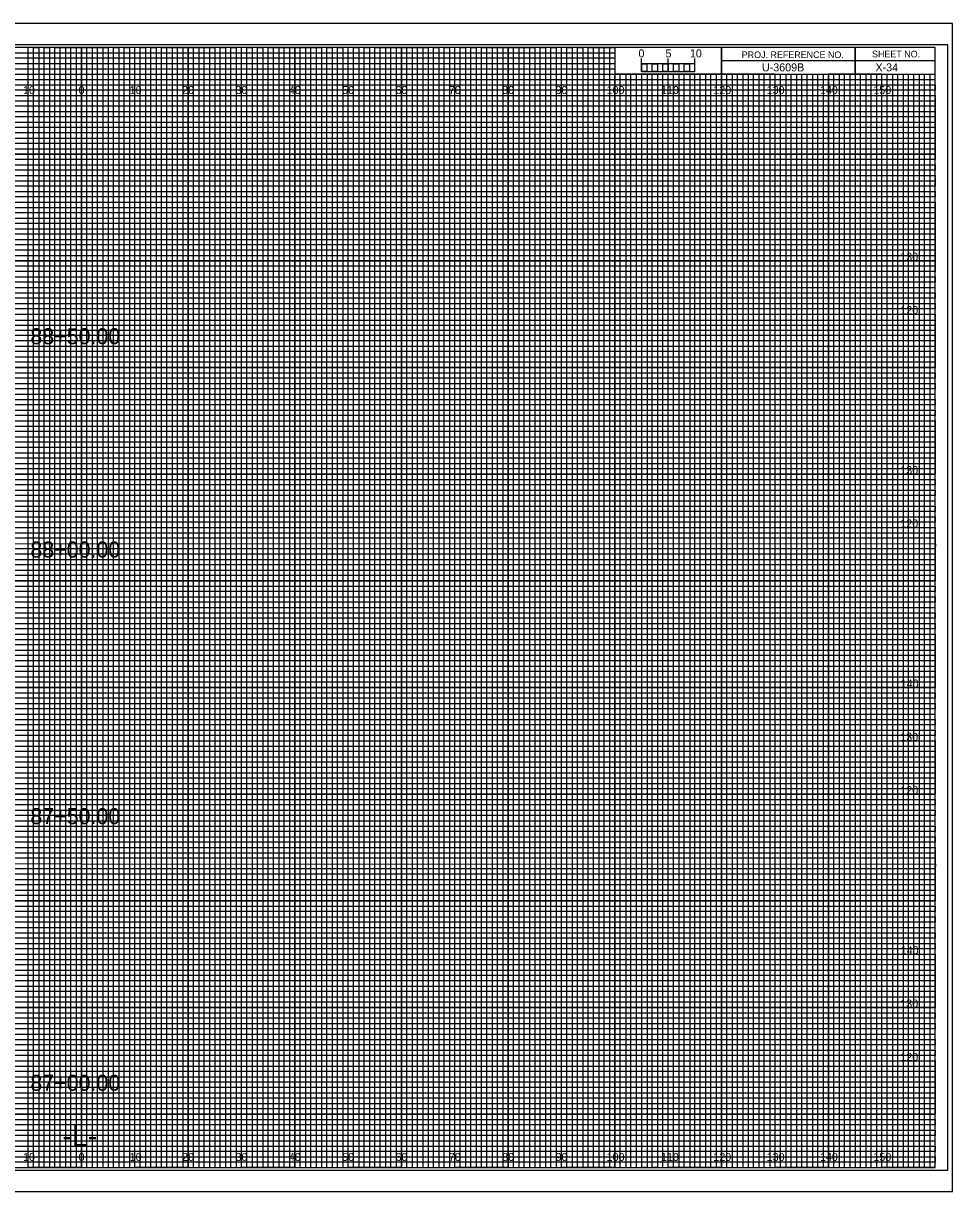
# Model space of a CAD drawing. Extents: x -13 to 329, y -17 to 10994.
# Drawn here: x 149.1 to 323.3, y 7035.5 to 7254.5 of the extents above; entities that cross this region are included whole.
import ezdxf

# ---------------------------------------------------------------- set-up
doc = ezdxf.new("R2010")
doc.units = 0
for name, color, linetype in [('Prop XS Alignment Label', 7, 'Continuous'), ('Prop XS Bar Scale Labels', 7, 'Continuous'), ('Prop XS Elevation Labels', 7, 'Continuous'), ('Prop XS Offset Labels', 7, 'Continuous'), ('Prop XS Project Number', 7, 'Continuous'), ('Prop XS Sheet Number', 7, 'Continuous'), ('Prop XS Station Labels', 7, 'Continuous'), ('Sheet Cross Section CELL', 7, 'Continuous'), ('Sheet Cross Section Grid Major CELL', 7, 'Continuous'), ('Sheet Cross Section Grid Middle CELL', 7, 'Continuous'), ('Sheet Cross Section Grid Minor 1 CELL', 7, 'Continuous'), ('Sheet Cross Section Grid Minor 2 CELL', 7, 'Continuous'), ('Sheet Cross Section Scale CELL', 7, 'Continuous'), ('Sheet Cutting Line CELL', 7, 'Continuous'), ('Sheet DOT Grid CELL', 7, 'Continuous'), ('Sheet Plot Border Inside CELL', 7, 'Continuous'), ('Sheet Plot Border Outside CELL', 7, 'Continuous')]:
    doc.layers.add(name, color=color, linetype=linetype)

msp = doc.modelspace()

# ---------------------------------------------------------------- linework, layer by layer
at = {"layer": 'Sheet Cross Section CELL'}
for p, q in [((305, 7250), (305, 7245)), ((305, 7245), (305, 7250)), ((280, 7247.5), (280, 7245)), ((320, 7247.49), (280, 7247.49)), ((280, 7245), (320, 7245))]:
    msp.add_line(p, q, dxfattribs=at)
for points in [[(320, 7250), (0, 7250), (0, 7040), (320, 7040)], [(280, 7250), (260, 7250), (260, 7245.03), (280, 7245.03)], [(320, 7250), (280, 7250), (280, 7245), (320, 7245)]]:
    msp.add_lwpolyline(points, close=True, dxfattribs=at)
at = {"layer": 'Sheet Cross Section Grid Major CELL'}
for p, q in [((150, 7250), (140, 7250)), ((150, 7040), (150, 7250)), ((170, 7250), (160, 7250)), ((160, 7250), (160, 7040)), ((170, 7040), (170, 7250)), ((190, 7250), (180, 7250)), ((180, 7250), (180, 7040)), ((190, 7040), (190, 7250)), ((210, 7250), (200, 7250)), ((200, 7250), (200, 7040)), ((210, 7040), (210, 7250)), ((230, 7250), (220, 7250)), ((220, 7250), (220, 7040)), ((230, 7040), (230, 7250)), ((250, 7250), (240, 7250)), ((240, 7250), (240, 7040)), ((250, 7040), (250, 7250)), ((260, 7250), (260, 7040)), ((270, 7040), (270, 7245)), ((290, 7245), (280, 7245)), ((280, 7245), (280, 7040)), ((290, 7040), (290, 7245)), ((310, 7245), (300, 7245)), ((300, 7245), (300, 7040)), ((310, 7040), (310, 7245)), ((160, 7040), (150, 7040)), ((180, 7040), (170, 7040)), ((200, 7040), (190, 7040)), ((220, 7040), (210, 7040)), ((240, 7040), (230, 7040)), ((260, 7040), (250, 7040)), ((280, 7040), (270, 7040)), ((300, 7040), (290, 7040)), ((320, 7040), (310, 7040)), ((320, 7040), (320, 7040))]:
    msp.add_line(p, q, dxfattribs=at)
for points in [[(0, 7240), (320, 7240), (320, 7230), (0, 7230)], [(0, 7220), (320, 7220), (320, 7210), (0, 7210)], [(0, 7200), (320, 7200), (320, 7190), (0, 7190)], [(0, 7180), (320, 7180), (320, 7170), (0, 7170)], [(0, 7160), (320, 7160), (320, 7150), (0, 7150)], [(0, 7140), (320, 7140), (320, 7130), (0, 7130)], [(0, 7120), (320, 7120), (320, 7110), (0, 7110)], [(0, 7100), (320, 7100), (320, 7090), (0, 7090)], [(0, 7080), (320, 7080), (320, 7070), (0, 7070)], [(0, 7060), (320, 7060), (320, 7050), (0, 7050)]]:
    msp.add_lwpolyline(points, dxfattribs=at)
at = {"layer": 'Sheet Cross Section Grid Middle CELL'}
for points in [[(145, 7040), (155, 7040), (155, 7250), (165, 7250), (165, 7040), (175, 7040), (175, 7250), (185, 7250), (185, 7040), (195, 7040), (195, 7250), (205, 7250), (205, 7040), (215, 7040), (215, 7250), (225, 7250), (225, 7040), (235, 7040), (235, 7250), (245, 7250), (245, 7040), (255, 7040), (255, 7250), (259.93, 7250), (260, 7250), (260, 7245), (264.99, 7245), (264.99, 7040), (275, 7040), (275, 7245), (285, 7245), (285, 7040), (295, 7040), (295, 7245), (305, 7245), (305, 7040), (315, 7040), (315, 7245)], [(0, 7245), (275, 7245)], [(0, 7225), (320, 7225), (320, 7235), (0, 7235)], [(0, 7205), (320, 7205), (320, 7215), (0, 7215)], [(0, 7185), (320, 7185), (320, 7195), (0, 7195)], [(0, 7165), (320, 7165), (320, 7175), (0, 7175)], [(0, 7145), (320, 7145), (320, 7155), (0, 7155)], [(0, 7125), (320, 7125), (320, 7135), (0, 7135)], [(0, 7105), (320, 7105), (320, 7115), (0, 7115)], [(0, 7085), (320, 7085), (320, 7095), (0, 7095)], [(0, 7065), (320, 7065), (320, 7075), (0, 7075)], [(0, 7045), (320, 7045), (320, 7055), (0, 7055)]]:
    msp.add_lwpolyline(points, dxfattribs=at)
at = {"layer": 'Sheet Cross Section Grid Minor 1 CELL'}
for p, q in [((0, 7249), (260, 7249)), ((260, 7249), (260, 7247.98)), ((260, 7247.98), (0, 7247.98)), ((0, 7247), (260, 7247)), ((260, 7247), (260, 7245.89)), ((260, 7245.89), (0, 7245.89)), ((0, 7244), (320, 7244))]:
    msp.add_line(p, q, dxfattribs=at)
for points in [[(0, 7243), (270, 7243), (320, 7243), (320, 7242), (0, 7242)], [(0, 7241), (320, 7241), (320, 7239), (0, 7239)], [(0, 7238), (320, 7238), (320, 7237), (0, 7236.98)], [(0, 7236), (320, 7236), (320, 7234), (0, 7234)], [(0, 7233), (320, 7233), (320, 7232), (0, 7232)], [(0, 7231), (320, 7231), (320, 7229), (0, 7229)], [(0, 7228), (320, 7228), (320, 7227), (0, 7227)], [(0, 7226), (320, 7226), (320, 7224), (0, 7224)], [(0, 7223), (320, 7223), (320, 7222), (0, 7222)], [(0, 7221), (320, 7221), (320, 7219), (0, 7219)], [(0, 7218), (320, 7218), (320, 7217), (0, 7217)], [(0, 7216), (320, 7216), (320, 7213.95), (320, 7213), (320, 7212), (0, 7212)], [(0, 7214), (320, 7214), (320, 7213), (0, 7213)], [(0, 7211), (320, 7211), (320, 7209), (0, 7209.03)], [(0, 7209.03), (320, 7209), (320, 7208), (0, 7208)], [(0, 7207), (320, 7207), (320, 7206), (0, 7206)], [(0, 7204), (320, 7204), (320, 7203), (0, 7203)], [(0, 7202), (320, 7202), (320, 7201), (0, 7201)], [(-0.07, 7198.89), (320, 7198.89), (320, 7197.88), (-0.07, 7197.88)], [(0, 7197), (320, 7197), (320, 7196), (0, 7196)], [(0, 7194), (320, 7194), (320, 7193), (0, 7193)], [(0, 7192), (320, 7192), (320, 7191), (0, 7191)], [(0, 7189), (320, 7189), (320, 7188), (0, 7188)], [(0, 7187), (320, 7187), (320, 7186), (0, 7186)], [(0, 7184), (320, 7184), (320, 7183), (0, 7183)], [(0, 7182), (320, 7182), (320, 7181), (0, 7181)], [(0, 7179), (320, 7179), (319.99, 7177.98), (0, 7178)], [(0, 7177), (320, 7177), (320, 7176), (0, 7176)], [(0, 7174), (320, 7174), (320, 7173), (0, 7173)], [(0, 7172), (320, 7172), (320, 7171), (0, 7171)], [(0, 7169), (320, 7169), (320, 7168), (0, 7168)], [(0, 7167), (320, 7167), (320, 7166), (0, 7166)], [(0, 7164), (320, 7164), (320, 7163), (0, 7163)], [(0, 7162), (320, 7162), (320, 7161), (0, 7161)], [(0, 7159), (320, 7159), (320, 7158), (0, 7158)], [(0, 7156.99), (320.07, 7156.91), (320, 7156), (0, 7156)], [(0, 7154), (320, 7154), (320, 7153), (0, 7153)], [(0, 7152), (320, 7152), (320, 7151), (0, 7151)], [(0, 7149), (320, 7149), (320, 7148), (0, 7148)], [(0, 7147), (320, 7147), (320, 7146), (0, 7146)], [(0, 7144), (320, 7144), (320, 7143), (0, 7143)], [(0, 7142), (320, 7142), (320, 7141), (0, 7141)], [(0, 7139), (320, 7139), (320, 7138), (0, 7138)], [(0, 7137), (320, 7137), (320, 7136), (0, 7136)], [(0, 7134), (320, 7134), (320, 7133), (0, 7133)], [(0, 7132), (320, 7132), (320, 7131), (0, 7131)], [(0, 7129), (320, 7129), (320, 7128), (0, 7128)], [(0, 7127), (320, 7127), (320, 7126), (0, 7126)], [(0, 7124), (320, 7124), (320, 7123), (0, 7123)], [(0, 7122), (320, 7122), (320, 7121), (0, 7121)], [(0, 7119), (320, 7119), (319.99, 7117.98), (0, 7118)], [(0, 7117), (320, 7117), (320, 7116), (0, 7116)], [(0, 7114), (320, 7114), (320, 7113), (0, 7113)], [(0, 7112), (320, 7112), (320, 7111), (0, 7111)], [(0, 7109), (320, 7109), (320, 7108), (0, 7108)], [(0, 7107), (320, 7107), (320, 7106), (0, 7106)], [(0, 7104), (320, 7104), (320, 7103), (0, 7103)], [(0, 7102), (320, 7102), (320, 7101), (0, 7101)], [(0, 7099), (320, 7099), (320, 7098), (0, 7098)], [(0, 7096.99), (320.07, 7096.91), (320, 7096), (0, 7096)], [(0, 7094), (320, 7094), (320, 7093), (0, 7093)], [(0, 7092), (320, 7092), (320, 7091), (0, 7091)], [(0, 7089), (320, 7089), (320, 7088), (0, 7088)], [(0, 7087), (320, 7087), (320, 7086), (0, 7086)], [(0, 7084), (320, 7084), (320, 7083), (0, 7083)], [(0, 7082), (320, 7082), (320, 7081), (0, 7081)], [(0, 7079), (320, 7079), (320, 7078), (0, 7078)], [(0, 7077), (320, 7077), (320, 7076), (0, 7076)], [(0, 7074), (320, 7074), (320, 7073), (0, 7073)], [(0, 7072), (320, 7072), (320, 7071), (0, 7071)], [(0, 7069), (320, 7069), (320, 7068), (0, 7068)], [(0, 7067), (320, 7067), (320, 7066), (0, 7066)], [(0, 7064), (320, 7064), (320, 7063), (0, 7063)], [(0, 7062), (320, 7062), (320, 7061), (0, 7061)], [(0, 7059), (320, 7059), (320, 7058), (0, 7058)], [(0, 7057), (320, 7057), (320, 7056), (0, 7056)], [(0, 7054), (320, 7054), (320, 7053), (0, 7053)], [(0, 7052), (320, 7052), (320, 7051), (0, 7051)], [(0, 7049), (320, 7049), (320, 7048), (0, 7048)], [(0, 7047), (320, 7047), (320, 7046), (0, 7046)], [(0, 7044), (320, 7044), (320, 7043), (0, 7043)], [(0, 7042), (320, 7042), (320, 7041), (0, 7041)]]:
    msp.add_lwpolyline(points, dxfattribs=at)
at = {"layer": 'Sheet Cross Section Grid Minor 2 CELL'}
for p, q in [((267, 7245), (266.01, 7245)), ((266.01, 7245), (266.01, 7040)), ((267, 7040), (267, 7245)), ((269, 7245), (268, 7245)), ((268, 7245), (268, 7040)), ((269, 7040), (269, 7245)), ((266.01, 7040), (265, 7040)), ((268, 7040), (267, 7040))]:
    msp.add_line(p, q, dxfattribs=at)
for points in [[(150, 7040), (151, 7040), (151, 7250), (152, 7250), (152, 7040)], [(152, 7040), (153, 7040), (153, 7250), (154, 7250), (154, 7040)], [(155, 7040), (156, 7040), (156, 7250), (157, 7250), (157, 7040)], [(157, 7040), (158, 7040), (158, 7250), (159, 7250), (159, 7040)], [(160, 7040), (161, 7040), (161, 7250), (162, 7250), (162, 7040)], [(162, 7040), (163, 7040), (163, 7250), (164, 7250), (164, 7040)], [(165, 7040), (166, 7040), (166, 7250), (167, 7250), (167, 7040)], [(167, 7040), (168, 7040), (168, 7250), (169, 7250), (169, 7040)], [(170, 7040), (171, 7040), (171, 7250), (172, 7250), (172, 7040)], [(172, 7040), (173, 7040), (173, 7250), (174, 7250), (174, 7040)], [(175, 7040), (176, 7040), (176, 7250), (177, 7250), (177, 7040)], [(177, 7040), (178, 7040), (178, 7250), (179, 7250), (179, 7040)], [(180, 7040), (181, 7040), (181, 7250), (182, 7250), (182, 7040)], [(182, 7040), (183, 7040), (183, 7250), (184, 7250), (184, 7040)], [(185, 7040), (186, 7040), (186, 7250), (187, 7250), (187, 7040)], [(187, 7040), (188, 7040), (188, 7250), (189, 7250), (189, 7040)], [(190, 7040), (191, 7040), (191, 7250), (192, 7250), (192, 7040)], [(192, 7040), (193, 7040), (193, 7250), (194, 7250), (194, 7040)], [(195, 7040), (196, 7040), (196, 7250), (197, 7250), (197, 7040)], [(197, 7040), (198, 7040), (198, 7250), (199, 7250), (199, 7040)], [(200, 7040), (201, 7040), (201, 7250), (202, 7250), (202, 7040)], [(202, 7040), (203, 7040), (203, 7250), (204, 7250), (204, 7040)], [(205, 7040), (206, 7040), (206, 7250), (207, 7250), (207, 7040)], [(207, 7040), (208, 7040), (208, 7250), (209, 7250), (209, 7040)], [(210, 7040), (211, 7040), (211, 7250), (212, 7250), (212, 7040)], [(212, 7040), (213, 7040), (213, 7250), (214, 7250), (214, 7040)], [(215, 7040), (216, 7040), (216, 7250), (217, 7250), (217, 7040)], [(217, 7040), (218, 7040), (218, 7250), (219, 7250), (219, 7040)], [(220, 7040), (221, 7040), (221, 7250), (222, 7250), (222, 7040)], [(222, 7040), (223, 7040), (223, 7250), (224, 7250), (224, 7040)], [(225, 7040), (226, 7040), (226, 7250), (227, 7250), (227, 7040)], [(227, 7040), (228, 7040), (228, 7250), (229, 7250), (229, 7040)], [(230, 7040), (231, 7040), (231, 7250), (232, 7250), (232, 7040)], [(232, 7040), (233, 7040), (233, 7250), (234, 7250), (234, 7040)], [(235, 7040), (236, 7040), (236, 7250), (237, 7250), (237, 7040)], [(237, 7040), (238, 7040), (238, 7250), (239, 7250), (239, 7040)], [(240, 7040), (241, 7040), (241, 7250), (242, 7250), (242, 7040)], [(242, 7040), (243, 7040), (243, 7250), (244, 7250), (244, 7040)], [(245, 7040), (246, 7040), (246, 7250), (247, 7250), (247, 7040)], [(247, 7040), (248, 7040), (248, 7250), (249, 7250), (249, 7040)], [(250, 7040), (251, 7040), (251, 7250), (252, 7250), (252, 7040)], [(252, 7040), (253, 7040), (253, 7250), (254, 7250), (254, 7040)], [(255, 7040), (256, 7040), (256, 7250), (257, 7250), (257, 7040)], [(257, 7040), (258, 7040), (258, 7250), (259, 7250), (259, 7040)], [(260, 7040), (261, 7040), (261, 7245), (262.02, 7245), (262.02, 7040)], [(262, 7040), (263, 7040), (263, 7245), (263.99, 7245), (263.99, 7040)], [(270, 7040), (270.98, 7040), (270.98, 7245), (272, 7245), (272, 7040)], [(272, 7040), (273, 7040), (273, 7245), (274.05, 7245), (274.05, 7040)], [(275, 7040), (276, 7040), (276, 7245), (277, 7245), (277, 7040)], [(277, 7040), (278, 7040), (278, 7245), (279, 7245), (279, 7040)], [(280, 7040), (281, 7040), (281, 7245), (282, 7245), (282, 7040)], [(282, 7040), (283, 7040), (283, 7245), (284, 7245), (284, 7040)], [(285, 7040), (286, 7040), (286, 7245), (287, 7245), (287, 7040)], [(287, 7040), (288, 7040), (288, 7245), (289, 7245), (289, 7040)], [(290, 7040), (291, 7040), (291, 7245), (292, 7245), (292, 7040)], [(292, 7040), (293, 7040), (293, 7245), (294, 7245), (294, 7040)], [(295, 7040), (296, 7040), (296, 7245), (297, 7245), (297, 7040)], [(297, 7040), (298, 7040), (298, 7245), (299, 7245), (299, 7040)], [(300, 7040), (301, 7040), (301, 7245), (302, 7245), (302, 7040)], [(302, 7040), (303, 7040), (303, 7245), (304, 7245), (304, 7040)], [(305, 7040), (306, 7040), (306, 7245), (307, 7245), (307, 7040)], [(307, 7040), (308, 7040), (308, 7245), (309, 7245), (309, 7040)], [(310, 7040), (311, 7040), (311, 7245), (312, 7245), (312, 7040)], [(312, 7040), (313, 7040), (313, 7245), (314, 7245), (314, 7040)], [(315, 7040), (316, 7040), (316, 7245), (317, 7245), (317, 7040)], [(317, 7040), (318, 7040), (318, 7245), (319, 7245), (319, 7040)]]:
    msp.add_lwpolyline(points, dxfattribs=at)
at = {"layer": 'Sheet Cross Section Scale CELL'}
for p, q in [((265, 7245.49), (265, 7247.9)), ((265, 7246.9), (265, 7247.9)), ((270, 7245.49), (270, 7247.9)), ((275, 7245.49), (275, 7247.9)), ((275, 7246.9), (275, 7247.9))]:
    msp.add_line(p, q, dxfattribs=at)
for points in [[(275, 7246.9), (265, 7246.9), (265, 7245.49), (275, 7245.49)], [(265, 7246.9), (266, 7246.9), (266, 7245.49), (265, 7245.49)], [(267, 7246.9), (268, 7246.9), (268, 7245.49), (267, 7245.49)], [(269, 7246.9), (270, 7246.9), (270, 7245.49), (269, 7245.49)], [(271, 7246.9), (272, 7246.9), (272, 7245.49), (271, 7245.49)], [(273, 7246.9), (274, 7246.9), (274, 7245.49), (273, 7245.49)]]:
    msp.add_lwpolyline(points, close=True, dxfattribs=at)
at = {"layer": 'Sheet Cutting Line CELL'}
for p, q in [((323.3, 7254.5), (-13.4, 7254.5)), ((-13.4, 7035.5), (323.3, 7035.5))]:
    msp.add_line(p, q, dxfattribs=at)
at = {"layer": 'Sheet DOT Grid CELL'}
for p, q in [((150, 7040), (150, 7250)), ((160, 7040), (160, 7250)), ((170, 7040), (170, 7250)), ((180, 7040), (180, 7250)), ((190, 7040), (190, 7250)), ((200, 7040), (200, 7250)), ((210, 7040), (210, 7250)), ((220, 7040), (220, 7250)), ((230, 7040), (230, 7250)), ((240, 7040), (240, 7250)), ((250, 7040), (250, 7250)), ((260, 7040), (260, 7244.69)), ((270, 7040), (270, 7244.69)), ((280, 7040), (280, 7244.69)), ((290, 7040), (290, 7244.69)), ((300, 7040), (300, 7244.69)), ((310, 7040), (310, 7244.69)), ((0, 7240), (320, 7240)), ((0, 7230), (320, 7230)), ((0, 7220), (320, 7220)), ((0, 7210), (320, 7210)), ((0, 7200), (320, 7200)), ((0, 7190), (320, 7190)), ((0, 7180), (320, 7180)), ((0, 7170), (320, 7170)), ((0, 7160), (320, 7160)), ((0, 7150), (320, 7150)), ((0, 7140), (320, 7140)), ((0, 7130), (320, 7130)), ((0, 7120), (320, 7120)), ((0, 7110), (320, 7110)), ((0, 7100), (320, 7100)), ((0, 7090), (320, 7090)), ((0, 7080), (320, 7080)), ((0, 7070), (320, 7070)), ((0, 7060), (320, 7060)), ((0, 7050), (320, 7050))]:
    msp.add_line(p, q, dxfattribs=at)
at = {"layer": 'Sheet Plot Border Inside CELL'}
msp.add_lwpolyline([(-10.8, 7039.5), (322.4, 7039.5), (322.4, 7250.5), (-10.8, 7250.5)], close=True, dxfattribs=at)
at = {"layer": 'Sheet Plot Border Outside CELL'}
msp.add_lwpolyline([(-13.4, 7035.5), (323.3, 7035.5), (323.3, 7254.5), (-13.4, 7254.5)], close=True, dxfattribs=at)

# ---------------------------------------------------------------- texts
at = {"layer": 'Prop XS Alignment Label'}
msp.add_text('-L-', height=4, dxfattribs=at).set_placement((156.42, 7044))
at = {"layer": 'Prop XS Bar Scale Labels'}
for s, p in [('5', (269.47, 7248.12)), ('10', (274.04, 7248.12))]:
    msp.add_text(s, height=1.5, dxfattribs=at).set_placement(p)
at = {"layer": 'Prop XS Elevation Labels'}
for s, p in [('130', (313.49, 7210)), ('120', (313.5, 7200)), ('130', (313.49, 7170)), ('120', (313.5, 7160)), ('140', (313.57, 7130)), ('130', (313.49, 7120)), ('120', (313.5, 7110)), ('140', (313.57, 7080)), ('130', (313.49, 7070)), ('120', (313.5, 7060))]:
    msp.add_text(s, height=1.5, dxfattribs=at).set_placement(p)
at = {"layer": 'Prop XS Offset Labels'}
for s, p in [('10', (149.04, 7241.25)), ('0', (159.45, 7241.25)), ('0', (159.45, 7241.25)), ('10', (169.04, 7241.25)), ('20', (178.86, 7241.25)), ('30', (188.86, 7241.25)), ('40', (198.86, 7241.25)), ('50', (208.86, 7241.25)), ('60', (218.86, 7241.25)), ('70', (228.86, 7241.25)), ('80', (238.86, 7241.25)), ('90', (248.86, 7241.25)), ('100', (258.44, 7241.25)), ('110', (268.62, 7241.25)), ('120', (278.44, 7241.25)), ('130', (288.44, 7241.25)), ('140', (298.44, 7241.25)), ('150', (308.44, 7241.25)), ('10', (149.04, 7041.25)), ('0', (159.45, 7041.25)), ('0', (159.45, 7041.25)), ('10', (169.04, 7041.25)), ('20', (178.86, 7041.25)), ('30', (188.86, 7041.25)), ('40', (198.86, 7041.25)), ('50', (208.86, 7041.25)), ('60', (218.86, 7041.25)), ('70', (228.86, 7041.25)), ('80', (238.86, 7041.25)), ('90', (248.86, 7041.25)), ('100', (258.44, 7041.25)), ('110', (268.62, 7041.25)), ('120', (278.44, 7041.25)), ('130', (288.44, 7041.25)), ('140', (298.44, 7041.25)), ('150', (308.44, 7041.25))]:
    msp.add_text(s, height=1.5, dxfattribs=at).set_placement(p)
at = {"layer": 'Prop XS Project Number'}
msp.add_text('U-3609B', height=1.5, dxfattribs=at).set_placement((287.56, 7245.5))
at = {"layer": 'Prop XS Sheet Number'}
msp.add_text('X-34', height=1.5, dxfattribs=at).set_placement((308.83, 7245.5))
at = {"layer": 'Prop XS Station Labels'}
for s, p in [('88+50.00', (150.41, 7194.35)), ('88+00.00', (150.41, 7154.37)), ('87+50.00', (150.41, 7104.39)), ('87+00.00', (150.41, 7054.41))]:
    msp.add_text(s, height=3, dxfattribs=at).set_placement(p)
at = {"layer": 'Sheet Cross Section CELL'}
for s, p in [('PROJ. REFERENCE NO.', (283.77, 7247.99)), ('SHEET NO.', (308.19, 7248.12))]:
    msp.add_text(s, height=1.25, dxfattribs=at).set_placement(p)
at = {"layer": 'Sheet Cross Section Scale CELL'}
msp.add_text('0', height=1.5, dxfattribs=at).set_placement((264.41, 7248.12))

doc.saveas('drawing.dxf')
